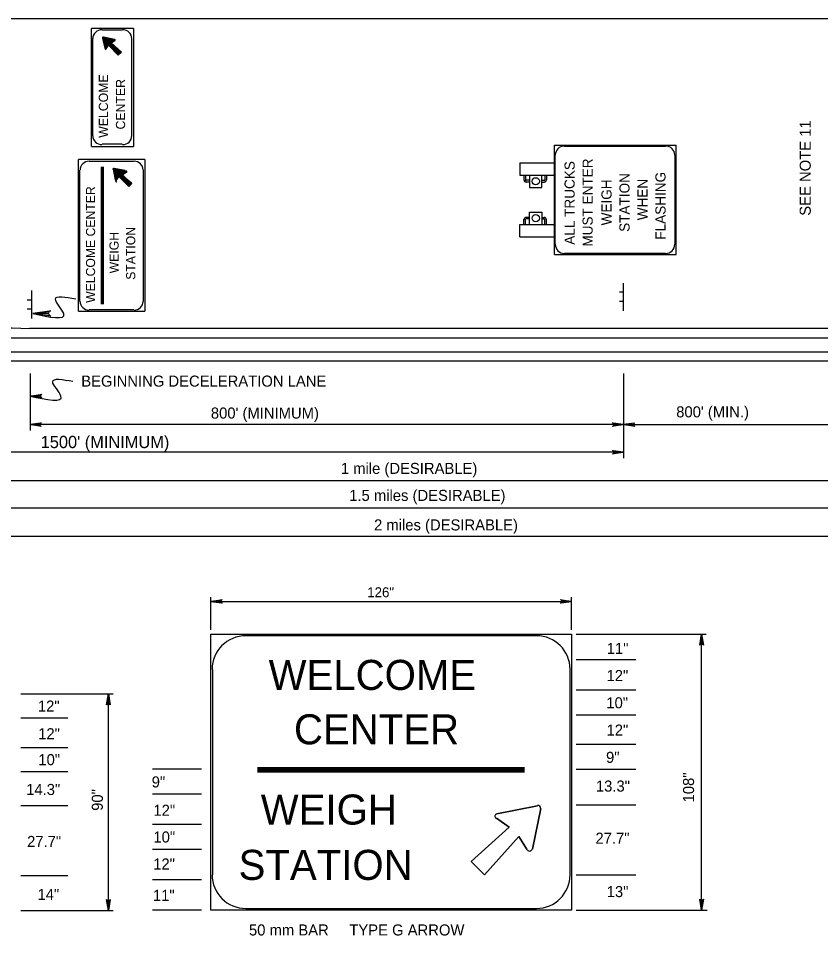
# Model space of a CAD drawing. Extents: x 638689 to 652291, y 298458 to 299646.
# Drawn here: x 651753 to 651970.5, y 298788.1 to 299036.7 of the extents above; entities that cross this region are included whole.
import ezdxf

# ---------------------------------------------------------------- set-up
doc = ezdxf.new("R2010")
doc.units = 0
for name, color, linetype in [('1', 7, 'Continuous'), ('2', 7, 'Continuous'), ('3', 7, 'Continuous')]:
    doc.layers.add(name, color=color, linetype=linetype)

# ---------------------------------------------------------------- blocks, each defined once
blk = doc.blocks.new('RARROW')
at = {"layer": '3'}
blk.add_lwpolyline([(-2.2695, 0.285), (-2.184875, 0.12075), (0, 0), (-2.2695, 0.285), (-2.38575, 0.384625), (0, 0), (-2.183125, -0.108), (-2.262875, -0.2705), (0, 0), (-2.38575, -0.379125), (-2.262875, -0.2705)], dxfattribs=at)

msp = doc.modelspace()

# ---------------------------------------------------------------- linework, layer by layer
at = {"layer": '1'}
msp.add_line((651426.31, 299036.75), (652212.31, 299036.75), dxfattribs=at)
at = {"layer": '2'}
for p, q in [((651772.81, 299002), (651772.81, 299034)), ((651784.19, 299034), (651772.81, 299034)), ((651784.19, 299034), (651784.19, 299002)), ((651773.19, 299004.87), (651773.19, 299031.25)), ((651775.69, 299033.62), (651781.19, 299033.62)), ((651775.81, 299031.62), (651775.81, 299031.62)), ((651775.81, 299031.37), (651776.44, 299028.62)), ((651779.06, 299031), (651776.06, 299031.62)), ((651783.69, 299031.25), (651783.69, 299004.87)), ((651776.81, 299028.5), (651777.44, 299029.5)), ((651777.44, 299029.5), (651777.44, 299029.5)), ((651777.44, 299029.5), (651780.06, 299026.75)), ((651777.81, 299029.75), (651777.81, 299029.75)), ((651778.19, 299030.12), (651779.19, 299030.75)), ((651778.19, 299030.12), (651779.19, 299030.75)), ((651778.19, 299030.12), (651778.19, 299030.12)), ((651780.94, 299027.62), (651778.19, 299030.12)), ((651779.56, 299031), (651779.56, 299031)), ((651776.56, 299028.12), (651776.56, 299028.12)), ((651780.06, 299026.75), (651780.94, 299027.62)), ((651780.06, 299026.75), (651780.06, 299026.75)), ((651780.94, 299027.62), (651780.94, 299027.62)), ((651772.81, 299002), (651784.19, 299002)), ((651781.19, 299002.62), (651775.69, 299002.62)), ((651898.31, 298972.75), (651898.31, 299002.37)), ((651898.31, 299002.37), (651931.31, 299002.37)), ((651901.06, 299002.12), (651928.44, 299002.12)), ((651931.31, 298972.75), (651931.31, 299002.37)), ((651898.56, 298975.5), (651898.56, 298999.62)), ((651930.94, 298999.62), (651930.94, 298975.5)), ((651769.31, 298957.37), (651769.31, 298998.5)), ((651787.31, 298998.5), (651769.31, 298998.5)), ((651772.19, 298998), (651784.31, 298998)), ((651775.56, 298959.25), (651775.56, 298996.5)), ((651775.69, 298959.25), (651775.69, 298996.5)), ((651775.81, 298959.25), (651775.81, 298996.5)), ((651775.94, 298959.25), (651775.94, 298996.5)), ((651776.06, 298959.25), (651776.06, 298996.5)), ((651787.31, 298998.5), (651787.31, 298957.37)), ((651888.94, 298997.62), (651888.94, 298994.25)), ((651888.94, 298997.62), (651898.31, 298997.62)), ((651769.69, 298960), (651769.69, 298995.62)), ((651778.56, 298996.12), (651778.56, 298996.12)), ((651778.69, 298995.87), (651779.31, 298993)), ((651781.94, 298995.5), (651778.94, 298996)), ((651780.56, 298994.12), (651780.56, 298994.12)), ((651780.94, 298994.5), (651782.06, 298995.12)), ((651780.94, 298994.5), (651782.06, 298995.12)), ((651780.94, 298994.5), (651780.94, 298994.5)), ((651783.81, 298992), (651780.94, 298994.5)), ((651781.19, 298994.25), (651782.31, 298995.12)), ((651781.19, 298994.25), (651781.19, 298994.25)), ((651782.44, 298995.37), (651782.44, 298995.37)), ((651786.81, 298995.62), (651786.81, 298960)), ((651888.94, 298994.25), (651891.56, 298994.25)), ((651890.06, 298994.25), (651890.06, 298993)), ((651890.44, 298994.25), (651890.44, 298993)), ((651891.56, 298994.25), (651891.56, 298990.87)), ((651891.56, 298994.25), (651898.31, 298994.25)), ((651894.94, 298990.87), (651894.94, 298994.25)), ((651895.69, 298994.25), (651895.69, 298993)), ((651896.19, 298994.25), (651896.19, 298993)), ((651779.44, 298992.5), (651779.44, 298992.5)), ((651779.56, 298992.87), (651780.31, 298993.75)), ((651780.31, 298993.75), (651780.31, 298993.75)), ((651780.31, 298993.75), (651782.94, 298991.12)), ((651780.44, 298993.5), (651780.44, 298993.5)), ((651780.81, 298993.87), (651780.81, 298993.87)), ((651782.94, 298991.12), (651783.81, 298992)), ((651783.81, 298992), (651783.81, 298992)), ((651891.56, 298992.87), (651890.69, 298992.87)), ((651891.56, 298992.37), (651890.69, 298992.37)), ((651894.94, 298992.87), (651895.44, 298992.87)), ((651894.94, 298992.37), (651895.44, 298992.37)), ((651782.94, 298991.12), (651782.94, 298991.12)), ((651891.56, 298990.87), (651894.94, 298990.87)), ((651891.56, 298980.87), (651891.56, 298984.25)), ((651891.56, 298984.25), (651894.94, 298984.25)), ((651894.94, 298984.25), (651894.94, 298980.87)), ((651890.06, 298980.87), (651890.06, 298982.25)), ((651890.44, 298980.87), (651890.44, 298982.25)), ((651891.56, 298982.75), (651890.69, 298982.75)), ((651891.56, 298982.37), (651890.69, 298982.37)), ((651894.94, 298982.75), (651895.44, 298982.75)), ((651894.94, 298982.37), (651895.44, 298982.37)), ((651895.69, 298980.87), (651895.69, 298982.25)), ((651896.19, 298980.87), (651896.19, 298982.25)), ((651888.94, 298977.5), (651888.94, 298980.87)), ((651888.94, 298980.87), (651891.56, 298980.87)), ((651891.56, 298980.87), (651898.31, 298980.87)), ((651888.94, 298977.5), (651898.31, 298977.5)), ((651898.31, 298972.75), (651931.31, 298972.75)), ((651928.44, 298973), (651901.06, 298973)), ((651917.06, 298957.5), (651917.06, 298965)), ((651756.69, 298955.37), (651756.69, 298963)), ((651917.06, 298962.5), (651915.94, 298962.5)), ((651756.69, 298960.37), (651755.44, 298960.37)), ((651917.06, 298960), (651915.94, 298960)), ((651756.69, 298957.87), (651755.44, 298957.87)), ((651769.31, 298957.37), (651787.31, 298957.37)), ((651784.31, 298957.75), (651772.19, 298957.75)), ((651756.06, 298952.75), (651756.06, 298952.75)), ((651756.06, 298952.75), (651756.06, 298952.75)), ((651756.06, 298952.75), (652211.31, 298952.75)), ((651429.31, 298950.12), (652211.31, 298950.12)), ((651429.31, 298946.37), (652211.31, 298946.37)), ((651429.31, 298943.87), (652211.31, 298943.87)), ((651756.19, 298940.5), (651756.19, 298925)), ((651917.06, 298940.5), (651917.06, 298917.5)), ((651917.06, 298926.62), (651756.19, 298926.62)), ((651917.06, 298926.62), (651978.67, 298926.62)), ((651917.06, 298919.12), (651680.69, 298919.12)), ((651680.69, 298911.5), (652031.94, 298911.5)), ((652084.69, 298904), (651680.69, 298904)), ((652137.56, 298896.25), (651680.69, 298896.25)), ((651805.21, 298870.95), (651805.21, 298879.82)), ((651902.96, 298870.95), (651902.96, 298879.82)), ((651805.21, 298878.7), (651902.96, 298878.7)), ((651805.21, 298869.82), (651902.96, 298869.82)), ((651805.21, 298794.95), (651805.21, 298869.82)), ((651902.96, 298869.82), (651902.96, 298794.95)), ((651904.21, 298869.82), (651914.21, 298869.82)), ((651904.21, 298869.82), (651914.21, 298869.82)), ((651910.96, 298869.82), (651939.46, 298869.82)), ((651938.21, 298794.95), (651938.21, 298869.82)), ((651893.46, 298869.32), (651814.71, 298869.32)), ((651904.21, 298862.95), (651920.4, 298862.95)), ((651805.59, 298860.2), (651805.59, 298804.57)), ((651902.59, 298804.57), (651902.59, 298860.2)), ((651904.21, 298854.7), (651920.4, 298854.7)), ((651753.69, 298853.62), (651778.67, 298853.62)), ((651777.42, 298794.87), (651777.42, 298853.62)), ((651904.21, 298847.95), (651920.4, 298847.95)), ((651753.69, 298847.12), (651766.44, 298847.12)), ((651904.21, 298839.95), (651920.4, 298839.95)), ((651753.69, 298839.12), (651766.44, 298839.12)), ((651753.69, 298832.62), (651766.44, 298832.62)), ((651802.68, 298833.2), (651789.38, 298833.2)), ((651817.84, 298833.7), (651890.21, 298833.7)), ((651817.84, 298833.45), (651890.21, 298833.45)), ((651817.84, 298833.2), (651890.21, 298833.2)), ((651817.84, 298832.95), (651890.21, 298832.95)), ((651817.84, 298832.7), (651890.21, 298832.7)), ((651817.84, 298832.45), (651890.21, 298832.45)), ((651904.21, 298833.2), (651920.4, 298833.2)), ((651802.68, 298826.45), (651789.38, 298826.45)), ((651753.69, 298823.37), (651766.44, 298823.37)), ((651893.71, 298823.32), (651882.71, 298821.07)), ((651882.71, 298821.07), (651893.71, 298823.32)), ((651892.34, 298811.57), (651894.59, 298822.57)), ((651894.59, 298822.57), (651892.34, 298811.57)), ((651894.84, 298823.57), (651894.84, 298823.57)), ((651904.21, 298823.57), (651920.4, 298823.57)), ((651881.09, 298820.82), (651881.09, 298820.82)), ((651882.59, 298819.95), (651886.09, 298817.45)), ((651886.09, 298817.45), (651882.59, 298819.95)), ((651802.68, 298818.2), (651789.38, 298818.2)), ((651886.09, 298817.45), (651875.71, 298808.2)), ((651875.71, 298808.2), (651886.09, 298817.45)), ((651886.09, 298817.45), (651875.71, 298808.2)), ((651875.71, 298808.2), (651886.09, 298817.45)), ((651886.09, 298817.45), (651886.09, 298817.45)), ((651886.09, 298817.45), (651886.09, 298817.45)), ((651879.34, 298804.57), (651888.71, 298814.95)), ((651888.71, 298814.95), (651879.34, 298804.57)), ((651887.34, 298816.32), (651887.34, 298816.32)), ((651887.34, 298816.32), (651887.34, 298816.32)), ((651888.71, 298814.95), (651888.71, 298814.95)), ((651888.71, 298814.95), (651888.71, 298814.95)), ((651888.71, 298814.95), (651890.96, 298811.32)), ((651890.96, 298811.32), (651888.71, 298814.95)), ((651802.68, 298811.45), (651789.38, 298811.45)), ((651891.84, 298809.95), (651891.84, 298809.95)), ((651875.71, 298808.2), (651875.71, 298808.2)), ((651875.71, 298808.2), (651875.71, 298808.2)), ((651875.71, 298808.2), (651879.34, 298804.57)), ((651879.34, 298804.57), (651875.71, 298808.2)), ((651753.69, 298804.37), (651766.44, 298804.37)), ((651802.68, 298803.2), (651789.38, 298803.2)), ((651879.34, 298804.57), (651879.34, 298804.57)), ((651879.34, 298804.57), (651879.34, 298804.57)), ((651904.21, 298804.57), (651920.4, 298804.57)), ((651814.71, 298795.45), (651893.46, 298795.45)), ((651753.69, 298794.87), (651778.67, 298794.87)), ((651802.68, 298794.95), (651789.38, 298794.95)), ((651902.96, 298794.95), (651805.21, 298794.95)), ((651904.21, 298794.95), (651939.74, 298794.95))]:
    msp.add_line(p, q, dxfattribs=at)
for points in [[(651780.81, 299027.62), (651780.06, 299026.87), (651777.44, 299029.62), (651776.81, 299028.62), (651776.69, 299028.62), (651776.56, 299028.62), (651775.94, 299031.37), (651776.06, 299031.5), (651779.19, 299030.87), (651778.06, 299030.12), (651780.81, 299027.62), (651780.06, 299027), (651777.44, 299029.62), (651776.69, 299028.75), (651776.69, 299028.62), (651776.06, 299031.37), (651779.06, 299030.87), (651778.06, 299030.12), (651780.69, 299027.62), (651780.19, 299027.12), (651777.44, 299029.75), (651776.69, 299028.87), (651776.19, 299031.25), (651778.81, 299030.75), (651777.81, 299030.12), (651780.56, 299027.62), (651780.19, 299027.25), (651777.44, 299029.75), (651776.81, 299029), (651776.31, 299031.12), (651778.56, 299030.75), (651777.81, 299030.12), (651780.44, 299027.62), (651780.19, 299027.37), (651777.44, 299029.87), (651776.94, 299029.25), (651776.56, 299031), (651778.44, 299030.62), (651777.56, 299030.12), (651780.31, 299027.62), (651780.19, 299027.62), (651777.44, 299030), (651776.94, 299029.5), (651776.69, 299030.87), (651778.19, 299030.62), (651777.56, 299030.12), (651780.31, 299027.75), (651780.19, 299027.62), (651780.19, 299027.5), (651777.44, 299030.12), (651780.19, 299027.75), (651780.06, 299027.62), (651777.44, 299030.12), (651777.06, 299029.75), (651776.81, 299030.75), (651777.94, 299030.5), (651777.19, 299030), (651776.94, 299030.62), (651777.81, 299030.5), (651777.31, 299030.12), (651777.19, 299030.62), (651777.56, 299030.5), (651777.31, 299030.37), (651777.31, 299030.5), (651777.44, 299030.5)], [(651783.69, 298992.12), (651782.94, 298991.37), (651780.31, 298993.87), (651779.56, 298993), (651779.44, 298992.87), (651779.31, 298993), (651778.81, 298995.87), (651778.94, 298996), (651782.06, 298995.25), (651780.81, 298994.5), (651783.69, 298992.12), (651782.94, 298991.5), (651780.31, 298994), (651779.56, 298993), (651779.56, 298993), (651778.94, 298995.87), (651781.81, 298995.25), (651780.81, 298994.37), (651783.56, 298992.12), (651782.94, 298991.62), (651780.31, 298994.12), (651779.56, 298993.12), (651779.06, 298995.75), (651781.69, 298995.25), (651780.56, 298994.37), (651783.44, 298992.12), (651783.06, 298991.75), (651780.31, 298994.12), (651779.69, 298993.37), (651779.19, 298995.62), (651781.31, 298995.12), (651780.56, 298994.37), (651783.31, 298992.12), (651783.06, 298991.87), (651780.31, 298994.25), (651779.81, 298993.62), (651779.31, 298995.5), (651781.06, 298995.12), (651780.44, 298994.37), (651783.19, 298992.12), (651783.06, 298992), (651780.31, 298994.37), (651779.81, 298993.87), (651779.56, 298995.37), (651780.94, 298995.12), (651780.31, 298994.37), (651783.06, 298992.12), (651783.06, 298992), (651783.06, 298992), (651780.31, 298994.37), (651783.06, 298992.12), (651782.94, 298992), (651780.31, 298994.37), (651779.94, 298994), (651779.69, 298995.25), (651780.69, 298995), (651780.06, 298994.25), (651779.81, 298995.12), (651780.56, 298995), (651780.06, 298994.5), (651779.94, 298995), (651780.31, 298995), (651780.19, 298994.75), (651780.06, 298995), (651780.31, 298994.87)], [(651761.44, 298956.25), (651761.31, 298956.62), (651756.94, 298956.75), (651761.44, 298956.25), (651761.81, 298956), (651756.94, 298956.75), (651761.31, 298957), (651761.44, 298957.37), (651756.94, 298956.75), (651761.81, 298957.5), (651761.44, 298957.37)]]:
    msp.add_lwpolyline(points, dxfattribs=at)
for centre in [(651893.25, 298992.57), (651893.25, 298982.58)]:
    msp.add_circle(centre, 0.977, dxfattribs=at)
for centre, radius, start, end in [((651901.02, 298999.67), 2.47, 90, 180), ((651928.47, 298999.67), 2.47, 0, 90), ((651890.65, 298992.99), 0.613, 180, 270), ((651890.65, 298992.99), 0.223, 180, 270), ((651895.53, 298992.99), 0.223, 270, 0), ((651895.53, 298992.99), 0.613, 270, 0), ((651890.65, 298982.16), 0.613, 90, 180), ((651890.65, 298982.16), 0.223, 90, 180), ((651895.53, 298982.16), 0.613, 0, 90), ((651895.53, 298982.16), 0.223, 0, 90), ((651901.02, 298975.49), 2.47, 180, 270), ((651928.47, 298975.49), 2.47, 270, 0), ((651789.98, 300385.53), 1433.22, 265.6447, 268.64351), ((651814.67, 298860.26), 9.14, 90, 180), ((651893.41, 298860.26), 9.14, 0, 90), ((651893.88, 298822.72), 0.686, 348.2602, 101.7398), ((651893.88, 298822.72), 0.686, 348.2602, 101.7398), ((651882.86, 298820.43), 0.686, 101.7398, 236.6838), ((651882.86, 298820.43), 0.686, 101.7398, 236.6838), ((651891.59, 298811.71), 0.686, 213.3162, 348.2602), ((651891.59, 298811.71), 0.686, 213.3162, 348.2602), ((651814.67, 298804.6), 9.14, 180, 270), ((651893.41, 298804.6), 9.14, 270, 0)]:
    msp.add_arc(centre, radius, start, end, dxfattribs=at)
for centre, major_axis, start_param, end_param in [((651775.68, 299031.28), (-2.49, 0), 4.712389, 6.283185), ((651776.02, 299031.48), (-0.189, 0), 4.50749, 6.488084), ((651781.26, 299031.28), (2.49, 0), 0, 1.570796), ((651779.05, 299030.88), (0.189, 0), 5.293867, 7.649083), ((651776.65, 299028.6), (0.189, 0), 3.346491, 5.701707), ((651775.68, 299004.88), (-2.49, 0), 0, 1.570796), ((651781.26, 299004.88), (2.49, 0), 4.712389, 6.283185), ((651772.19, 298995.66), (-2.47, 0), 4.712389, 6.283185), ((651784.36, 298995.66), (2.47, 0), 0, 1.570796), ((651778.84, 298995.85), (-0.189, 0), 4.50749, 6.488084), ((651778.86, 298995.83), (-0.21, 0), 4.50749, 6.488084), ((651781.87, 298995.26), (0.189, 0), 5.293867, 7.649083), ((651782.23, 298995.17), (0.21, 0), 5.293867, 7.649083), ((651779.47, 298992.98), (0.189, 0), 3.346491, 5.701707), ((651779.56, 298992.63), (0.21, 0), 3.346491, 5.701707), ((651772.19, 298960.02), (-2.47, 0), 0, 1.570796), ((651784.36, 298960.02), (2.47, 0), 4.712389, 6.283185)]:
    msp.add_ellipse(centre, major_axis=major_axis, ratio=0.95, start_param=start_param, end_param=end_param, dxfattribs=at)
for points in [[(651756.94, 298956.75), (651765.31, 298956.75), (651763.06, 298960.62), (651768.56, 298960.75)], [(651756.19, 298934.37), (651764.56, 298934.37), (651762.31, 298938.25), (651767.81, 298938.37)]]:
    msp.add_spline(points, degree=3, dxfattribs=at)

# ---------------------------------------------------------------- block references
at = {"layer": '2', "xscale": 1.2574347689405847, "yscale": 1.3092961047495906}
for p, rotation in [((651756.36, 298934.37), 180), ((651756.19, 298926.62), 180), ((651917.06, 298926.62), 180), ((651805.21, 298878.7), 180), ((651938.21, 298869.82), 89.99999999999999), ((651777.42, 298853.62), 89.99999999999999), ((651777.42, 298794.87), -90.00000000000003), ((651938.21, 298794.95), -90.00000000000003)]:
    msp.add_blockref('RARROW', p, dxfattribs=dict(at, rotation=rotation))
for p in [(651917.06, 298926.62), (651917.06, 298919.12), (651902.96, 298878.7)]:
    msp.add_blockref('RARROW', p, dxfattribs=at)

# ---------------------------------------------------------------- texts
at = {"layer": '2'}
for s, height, p in [('WELCOME', 2.488, (651777.31, 299004.37)), ('CENTER', 2.488, (651781.94, 299006.62)), ('SEE NOTE 11', 3, (651967.8, 298983.24)), ('ALL TRUCKS', 2.749, (651903.81, 298975.37)), ('MUST ENTER', 2.749, (651908.69, 298974.87)), ('STATION', 2.749, (651918.69, 298978.87)), ('FLASHING', 2.749, (651928.44, 298976.75)), ('WEIGH', 2.749, (651913.81, 298980.62)), ('WHEN', 2.749, (651923.56, 298982)), ('WELCOME CENTER', 2.4728, (651773.81, 298959.62)), ('STATION', 2.473, (651784.69, 298965.87)), ('WEIGH', 2.473, (651780.19, 298967.62)), (' 108"', 3, (651936.17, 298823.09)), ('90"', 3, (651775.91, 298821.92))]:
    msp.add_text(s, height=height, rotation=90, dxfattribs=at).set_placement(p)
for s, height, p in [('BEGINNING DECELERATION LANE', 3, (651770.06, 298936.91)), ("800' (MINIMUM)", 3, (651805.19, 298928.25)), ("800' (MIN.)", 3, (651931.33, 298928.58)), ("1500' (MINIMUM)", 3.3188, (651759.06, 298920.25)), (' 1 mile (DESIRABLE)', 3, (651839.31, 298913.25)), ('1.5 miles (DESIRABLE)', 3, (651842.69, 298905.93)), ('2 miles (DESIRABLE)', 3, (651849.42, 298897.93)), ('126"', 2.7, (651847.56, 298879.82)), ('11"', 3, (651912.5, 298864.46)), ('WELCOME', 8.143, (651820.84, 298854.7)), ('12"', 3, (651912.44, 298857.09)), ('10"', 3, (651912.39, 298849.7)), ('12"', 3, (651758.3, 298848.82)), ('CENTER', 8.143, (651827.71, 298839.95)), ('12"', 3, (651912.44, 298842.31)), ('12"', 3, (651758.38, 298841.32)), ('10"', 3, (651758.43, 298834.29)), (' 9"', 3, (651911.19, 298834.93)), (' 9"', 3, (651788.04, 298828.26)), ('13.3"', 3, (651909.56, 298827.14)), ('14.3"', 3, (651755.12, 298826.21)), ('WEIGH', 8.143, (651818.71, 298818.2)), ('12"', 3, (651789.62, 298820.57)), ('27.7"', 3, (651755.37, 298812.12)), ('10"', 3, (651789.62, 298813.33)), ('27.7"', 3, (651909.44, 298813.01)), ('STATION', 8.143, (651812.71, 298803.2)), ('12"', 3, (651789.56, 298806.01)), ('14"', 3, (651758.19, 298797.75)), ('11"', 3, (651789.48, 298797.51)), ('13"', 3, (651912.49, 298798.53)), ('50 mm BAR     TYPE G ARROW', 3, (651815.52, 298788.13))]:
    msp.add_text(s, height=height, dxfattribs=at).set_placement(p)

doc.saveas('drawing.dxf')
